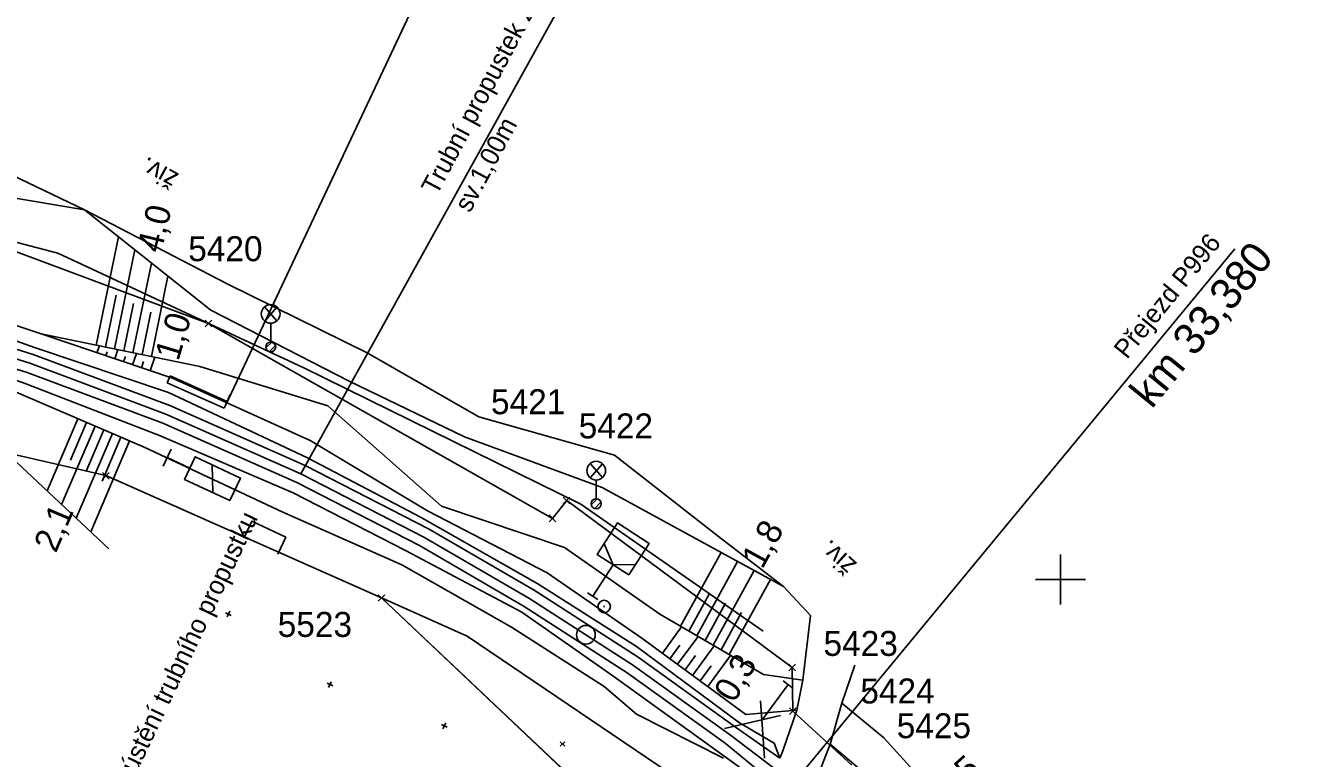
# Model space of a CAD drawing. Extents: x -805011 to -803920, y -1150790 to -1150234.
# Drawn here: x -804282.8 to -804179.8, y -1150514.3 to -1150455.7 of the extents above; entities that cross this region are included whole.
import ezdxf

# ---------------------------------------------------------------- set-up
doc = ezdxf.new("R2010")
doc.units = 0
for name, color, linetype in [('0381KM032-037P - Vrstva 1', 7, 'Continuous'), ('0381KM032-037P - Vrstva 17', 7, 'Continuous'), ('0381KM032-037P - Vrstva 19', 7, 'Continuous'), ('0381KM032-037P - Vrstva 25', 7, 'Continuous'), ('0381KM032-037P - Vrstva 4', 7, 'Continuous'), ('0381KM032-037P - Vrstva 43', 7, 'Continuous'), ('0381KM032-037P - Vrstva 48', 7, 'Continuous'), ('0381KM032-037P - Vrstva 49', 7, 'Continuous'), ('0381KM032-037P - Vrstva 51', 7, 'Continuous'), ('0381KM032-037P - Vrstva 55', 7, 'Continuous'), ('0381KM032-037P - Vrstva 7', 7, 'Continuous'), ('0381KM032-037P - Vrstva 9', 7, 'Continuous'), ('krizky_1000 - Vrstva 1', 7, 'Continuous'), ('szdc - hran DP', 7, 'Continuous'), ('szdc - szdc_cislo', 7, 'Continuous'), ('szdc - szdc_krizek', 7, 'Continuous')]:
    doc.layers.add(name, color=color, linetype=linetype)

msp = doc.modelspace()

# ---------------------------------------------------------------- linework, layer by layer
at = {"layer": '0381KM032-037P - Vrstva 1'}
msp.add_lwpolyline([(-804222.98, -1150515.09), (-804226.42, -1150512.48), (-804234.26, -1150506.83), (-804242.54, -1150501.49), (-804250.96, -1150496.61), (-804260.8, -1150491.55), (-804271.59, -1150486.76), (-804282.48, -1150482.69), (-804291.53, -1150479.85), (-804302.34, -1150477.08), (-804311.51, -1150475.27), (-804320.67, -1150473.88), (-804330.92, -1150472.81), (-804341.55, -1150472.27), (-804345.19, -1150472.22)], dxfattribs=at)
at = {"layer": '0381KM032-037P - Vrstva 17'}
msp.add_lwpolyline([(-804223.8, -1150504.14), (-804238.39, -1150493.96), (-804260.56, -1150483.05), (-804280.24, -1150473.89), (-804302.47, -1150468.07)], dxfattribs=at)
at = {"layer": '0381KM032-037P - Vrstva 19'}
msp.add_line((-804260.8, -1150491.55), (-804226.07, -1150428.82), dxfattribs=at)
at = {"layer": '0381KM032-037P - Vrstva 25'}
for p, q in [((-804263.7, -1150478.18), (-804262.71, -1150479.29)), ((-804263.69, -1150479.31), (-804262.71, -1150478.19)), ((-804263.21, -1150479.49), (-804263.21, -1150480.99)), ((-804263.6, -1150481.47), (-804263.13, -1150481)), ((-804263.33, -1150481.77), (-804262.83, -1150481.27)), ((-804237.65, -1150490.73), (-804236.66, -1150491.84)), ((-804237.64, -1150491.86), (-804236.66, -1150490.74)), ((-804237.16, -1150492.04), (-804237.16, -1150493.54)), ((-804237.55, -1150494.02), (-804237.08, -1150493.55)), ((-804237.28, -1150494.32), (-804236.78, -1150493.82))]:
    msp.add_line(p, q, dxfattribs=at)
for centre, radius in [((-804263.21, -1150478.74), 0.749), ((-804263.21, -1150481.39), 0.4), ((-804263.21, -1150481.39), 0.4), ((-804237.16, -1150491.29), 0.749), ((-804237.16, -1150493.94), 0.4), ((-804237.16, -1150493.94), 0.4)]:
    msp.add_circle(centre, radius, dxfattribs=at)
at = {"layer": '0381KM032-037P - Vrstva 4'}
for p, q in [((-804186.06, -1150473.54), (-804222.06, -1150517.12)), ((-804221.8, -1150508.42), (-804223.88, -1150511.23)), ((-804221.4, -1150508.72), (-804222.2, -1150508.12)), ((-804223.68, -1150514.31), (-804224, -1150509.71)), ((-804222.4, -1150510.9), (-804226.89, -1150511.93))]:
    msp.add_line(p, q, dxfattribs=at)
for points in [[(-804225.7, -1150511.47), (-804233.93, -1150505.38), (-804241.84, -1150500.35), (-804251.18, -1150495.03), (-804260.27, -1150490.25), (-804271.39, -1150485.02), (-804282.1, -1150481.42), (-804291.28, -1150478.15), (-804302, -1150475.62), (-804311.22, -1150473.82), (-804320.47, -1150472.35), (-804331.17, -1150471.28), (-804341.36, -1150470.84), (-804345.11, -1150470.79), (-804355.15, -1150471.09), (-804364.49, -1150471.64), (-804373.72, -1150472.46), (-804382.56, -1150473.46), (-804390.64, -1150474.3), (-804394.58, -1150474.82), (-804430.68, -1150479.4), (-804471.16, -1150484.87), (-804515.79, -1150490.21)], [(-804222.47, -1150514.31), (-804225.93, -1150511.88), (-804233.81, -1150506.22), (-804242.12, -1150500.85), (-804250.57, -1150495.96), (-804260.44, -1150490.89), (-804271.28, -1150486.07), (-804282.21, -1150481.99), (-804291.28, -1150479.14), (-804302.11, -1150476.36), (-804311.33, -1150474.54), (-804320.55, -1150473.14), (-804330.83, -1150472.06), (-804341.5, -1150471.52), (-804345.16, -1150471.47), (-804355.1, -1150471.64), (-804364.39, -1150472.17), (-804373.73, -1150473.02), (-804382.33, -1150473.97), (-804390.45, -1150474.97), (-804394.45, -1150475.48), (-804430.79, -1150480.07), (-804470.48, -1150485.06), (-804515.61, -1150490.8)], [(-804223.37, -1150515.97), (-804226.85, -1150513.1), (-804234.67, -1150507.48), (-804242.93, -1150502.16), (-804251.31, -1150497.29), (-804261.13, -1150492.25), (-804271.85, -1150487.49), (-804282.71, -1150483.42), (-804291.73, -1150480.59), (-804302.46, -1150477.85), (-804311.66, -1150476.01), (-804320.71, -1150474.65), (-804330.94, -1150473.58), (-804341.55, -1150473.05), (-804345.16, -1150472.99), (-804355.02, -1150473.16), (-804364.28, -1150473.69), (-804373.57, -1150474.51), (-804382.12, -1150475.46), (-804390.26, -1150476.46), (-804394.25, -1150476.96), (-804430.61, -1150481.56), (-804470.33, -1150486.56), (-804515.43, -1150492.3)], [(-804235.83, -1150507.71), (-804243.11, -1150502.63), (-804252.43, -1150497.68), (-804261.4, -1150493.06), (-804272.11, -1150488.47), (-804283.06, -1150484.22), (-804291.82, -1150481.32), (-804302.89, -1150478.85), (-804311.92, -1150476.81), (-804320.92, -1150475.47), (-804331.06, -1150474.34), (-804341.56, -1150473.81), (-804345.45, -1150473.75), (-804355.04, -1150473.96), (-804364.32, -1150474.45), (-804373.64, -1150475.34), (-804382.1, -1150476.35), (-804390.24, -1150477.29), (-804394.24, -1150477.85), (-804430.45, -1150482.3), (-804470.19, -1150487.36), (-804515.37, -1150493.06)], [(-804235.83, -1150507.71), (-804224.74, -1150515.72), (-804223.37, -1150515.97)], [(-804222.47, -1150514.31), (-804222.91, -1150513.11), (-804225.7, -1150511.47)]]:
    msp.add_lwpolyline(points, dxfattribs=at)
at = {"layer": '0381KM032-037P - Vrstva 43'}
msp.add_lwpolyline([(-804265.36, -1150496.69), (-804264.71, -1150495.33), (-804262, -1150496.62), (-804262.65, -1150497.98)], dxfattribs=at)
at = {"layer": '0381KM032-037P - Vrstva 48'}
for p, q in [((-804277.17, -1150481.25), (-804275.39, -1150472.58)), ((-804275.7, -1150481.55), (-804274.07, -1150473.62)), ((-804274.23, -1150481.85), (-804272.76, -1150474.67)), ((-804272.76, -1150482.15), (-804271.44, -1150475.71)), ((-804276.44, -1150481.4), (-804275.58, -1150477.25)), ((-804274.97, -1150481.7), (-804274.19, -1150477.92)), ((-804273.5, -1150482), (-804272.8, -1150478.59)), ((-804277.11, -1150481.85), (-804276.92, -1150481.3)), ((-804276.4, -1150482.09), (-804276.29, -1150481.77)), ((-804275.69, -1150482.33), (-804275.44, -1150481.6)), ((-804274.98, -1150482.57), (-804274.84, -1150482.16)), ((-804274.27, -1150482.81), (-804273.96, -1150481.91)), ((-804273.56, -1150483.05), (-804273.39, -1150482.55)), ((-804272.85, -1150483.29), (-804272.48, -1150482.21)), ((-804278.64, -1150487.13), (-804281.11, -1150492.91)), ((-804277.26, -1150487.72), (-804279.94, -1150494)), ((-804277.95, -1150487.43), (-804279.23, -1150490.44)), ((-804275.88, -1150488.31), (-804278.78, -1150495.09)), ((-804276.57, -1150488.02), (-804277.96, -1150491.28)), ((-804274.5, -1150488.9), (-804277.61, -1150496.19)), ((-804275.19, -1150488.6), (-804276.69, -1150492.12)), ((-804230.4, -1150503.75), (-804227.17, -1150497.84)), ((-804229.1, -1150504.51), (-804225.85, -1150498.56)), ((-804227.81, -1150505.26), (-804224.53, -1150499.28)), ((-804226.51, -1150506.02), (-804223.22, -1150500)), ((-804229.75, -1150504.13), (-804228.13, -1150501.17)), ((-804228.45, -1150504.88), (-804226.82, -1150501.9)), ((-804227.16, -1150505.64), (-804225.52, -1150502.64)), ((-804231.86, -1150505.91), (-804230.32, -1150503.8)), ((-804231.26, -1150506.35), (-804230.46, -1150505.26)), ((-804230.65, -1150506.79), (-804229.01, -1150504.56)), ((-804229.44, -1150507.68), (-804227.71, -1150505.32)), ((-804230.05, -1150507.24), (-804229.2, -1150506.09)), ((-804228.23, -1150508.57), (-804226.41, -1150506.08)), ((-804228.84, -1150508.12), (-804227.95, -1150506.91))]:
    msp.add_line(p, q, dxfattribs=at)
at = {"layer": '0381KM032-037P - Vrstva 49'}
for p, q in [((-804266.82, -1150502.66), (-804266.36, -1150502.88)), ((-804266.48, -1150502.54), (-804266.7, -1150503)), ((-804258.7, -1150508.31), (-804258.24, -1150508.53)), ((-804258.36, -1150508.19), (-804258.58, -1150508.65)), ((-804220.62, -1150508.07), (-804221.1, -1150510.47)), ((-804218.43, -1150513.19), (-804217.51, -1150509.9)), ((-804214.14, -1150512.69), (-804217.51, -1150509.9)), ((-804249.54, -1150511.61), (-804249.08, -1150511.83)), ((-804249.2, -1150511.49), (-804249.42, -1150511.95)), ((-804239.68, -1150513.36), (-804240.04, -1150513)), ((-804239.68, -1150513), (-804240.04, -1150513.36)), ((-804218.43, -1150513.19), (-804219.46, -1150515.79)), ((-804216.26, -1150515.03), (-804218.43, -1150513.19))]:
    msp.add_line(p, q, dxfattribs=at)
for points in [[(-804320.34, -1150463.27), (-804278.12, -1150470.41)], [(-804221.1, -1150510.47), (-804225.19, -1150510.8), (-804233.52, -1150504.69), (-804241.09, -1150499.46), (-804250.66, -1150494.51), (-804260.04, -1150488.87), (-804271.07, -1150483.89), (-804281.58, -1150480.34), (-804290.68, -1150477.29), (-804301.47, -1150474.53), (-804310.76, -1150472.67), (-804320.3, -1150471.51), (-804330.99, -1150470.46), (-804340.83, -1150469.83), (-804345.1, -1150470.19), (-804354.95, -1150469.89)], [(-804222.18, -1150500.57), (-804236.67, -1150492.64), (-804247.69, -1150488.59), (-804256.93, -1150484.13), (-804267.99, -1150478.45), (-804278.12, -1150470.41)], [(-804226.97, -1150514.32), (-804233.94, -1150510.78), (-804236.52, -1150508.57), (-804243.93, -1150503.82), (-804252.72, -1150498.82), (-804262.25, -1150494.6), (-804273.33, -1150489.4), (-804283.59, -1150485.01), (-804292.89, -1150482.47), (-804303.02, -1150479.68), (-804312.2, -1150478.16), (-804321.12, -1150476.62), (-804331.14, -1150475.24), (-804341.8, -1150475.06), (-804345.41, -1150474.87), (-804355.14, -1150475.34), (-804364.22, -1150475.73), (-804373.58, -1150476.33), (-804382.14, -1150477.38), (-804390.01, -1150478.23), (-804394.36, -1150478.78), (-804430.35, -1150482.91), (-804470.16, -1150488.05), (-804515.21, -1150493.93)], [(-804276.15, -1150497.56), (-804284.03, -1150490.16), (-804299.15, -1150485.83), (-804306.89, -1150483.98), (-804317.28, -1150482.7), (-804327.05, -1150481.84), (-804338.6, -1150481.41), (-804350.55, -1150480.59), (-804360.54, -1150481.11), (-804374.96, -1150483.29), (-804385.39, -1150485.41), (-804391.71, -1150485.5), (-804430.73, -1150489.32), (-804470.3, -1150492.85), (-804514.17, -1150497.56)], [(-804220.62, -1150508.07), (-804223.76, -1150507.62), (-804232.08, -1150502.77), (-804239.7, -1150497.43), (-804249.53, -1150494.12), (-804258.64, -1150486.1), (-804268.88, -1150482.95), (-804281.58, -1150480.34)], [(-804222.18, -1150500.57), (-804220.01, -1150502.88), (-804220.62, -1150508.07)], [(-804179.78, -1150547.3), (-804187.89, -1150541.65), (-804195.9, -1150532.8), (-804214.14, -1150512.69)]]:
    msp.add_lwpolyline(points, dxfattribs=at)
at = {"layer": '0381KM032-037P - Vrstva 51'}
for points in [[(-804222.47, -1150514.31), (-804222.23, -1150513.73), (-804221.1, -1150510.47), (-804220.62, -1150508.07), (-804220.01, -1150502.88), (-804222.18, -1150500.57), (-804227.38, -1150496.55), (-804235.69, -1150490.06), (-804246.55, -1150486.97), (-804255.48, -1150481.87), (-804266.7, -1150476.32), (-804278.12, -1150470.41), (-804293.62, -1150463)], [(-804219.78, -1150516.58), (-804219.46, -1150515.79), (-804218.43, -1150513.19), (-804217.51, -1150509.9), (-804216.47, -1150506.86)]]:
    msp.add_lwpolyline(points, dxfattribs=at)
at = {"layer": '0381KM032-037P - Vrstva 55'}
msp.add_lwpolyline([(-804254.35, -1150501.48), (-804247.48, -1150504.53), (-804225.97, -1150519.11), (-804228.6, -1150522.11), (-804232.32, -1150522.3)], close=True, dxfattribs=at)
at = {"layer": '0381KM032-037P - Vrstva 7'}
for p, q in [((-804271.17, -1150489.56), (-804271.81, -1150490.92)), ((-804267.9, -1150490.82), (-804267.84, -1150493.06)), ((-804235.81, -1150498.82), (-804237.44, -1150501.34)), ((-804237.86, -1150501.07), (-804237.02, -1150501.61)), ((-804236.57, -1150502.17), (-804236.47, -1150502.17))]:
    msp.add_line(p, q, dxfattribs=at)
for points in [[(-804271.49, -1150490.24), (-804269.68, -1150491.09), (-804270.1, -1150491.99), (-804266.48, -1150493.69), (-804265.63, -1150491.88), (-804269.25, -1150490.18), (-804269.68, -1150491.09)], [(-804235.81, -1150498.82), (-804234.55, -1150499.63), (-804232.93, -1150497.11), (-804235.45, -1150495.48), (-804237.07, -1150498.01), (-804235.81, -1150498.82)], [(-804236.53, -1150497.16), (-804235.81, -1150498.82), (-804234.01, -1150498.79)]]:
    msp.add_lwpolyline(points, dxfattribs=at)
for centre, radius in [((-804236.52, -1150502.17), 0.5), ((-804237.98, -1150504.43), 0.75)]:
    msp.add_circle(centre, radius, dxfattribs=at)
at = {"layer": '0381KM032-037P - Vrstva 9'}
for p, q in [((-804237.76, -1150424.25), (-804266.81, -1150486.01)), ((-804271.26, -1150483.71), (-804271.5, -1150484.26)), ((-804266.69, -1150485.74), (-804271.26, -1150483.71)), ((-804271.5, -1150484.26), (-804266.93, -1150486.28)), ((-804266.93, -1150486.28), (-804266.69, -1150485.74)), ((-804266.69, -1150485.74), (-804266.45, -1150485.19))]:
    msp.add_line(p, q, dxfattribs=at)
at = {"layer": 'krizky_1000 - Vrstva 1'}
for points in [[(-804200, -1150498), (-804200, -1150502)], [(-804202, -1150500), (-804198, -1150500)]]:
    msp.add_lwpolyline(points, dxfattribs=at)
at = {"layer": 'szdc - hran DP'}
for p, q in [((-804301.77, -1150466.98), (-804268.19, -1150479.5)), ((-804268.19, -1150479.5), (-804240.65, -1150495.11)), ((-804276.4, -1150491.69), (-804317.89, -1150482.17)), ((-804254.35, -1150501.48), (-804276.4, -1150491.69)), ((-804240.65, -1150495.11), (-804239.52, -1150493.68)), ((-804239.52, -1150493.68), (-804221.47, -1150507.06)), ((-804232.32, -1150522.3), (-804254.35, -1150501.48)), ((-804221.47, -1150507.06), (-804221.41, -1150510.55)), ((-804221.41, -1150510.55), (-804216.71, -1150514.88))]:
    msp.add_line(p, q, dxfattribs=at)
at = {"layer": 'szdc - szdc_krizek'}
for p, q in [((-804267.93, -1150479.77), (-804268.46, -1150479.24)), ((-804268.46, -1150479.77), (-804267.93, -1150479.24)), ((-804276.14, -1150491.96), (-804276.67, -1150491.43)), ((-804276.67, -1150491.96), (-804276.14, -1150491.43)), ((-804239.26, -1150493.95), (-804239.79, -1150493.42)), ((-804239.79, -1150493.95), (-804239.26, -1150493.42)), ((-804240.39, -1150495.38), (-804240.92, -1150494.84)), ((-804240.92, -1150495.38), (-804240.39, -1150494.84)), ((-804254.08, -1150501.75), (-804254.62, -1150501.22)), ((-804254.62, -1150501.75), (-804254.08, -1150501.22)), ((-804221.21, -1150507.32), (-804221.74, -1150506.79)), ((-804221.74, -1150507.32), (-804221.21, -1150506.79)), ((-804221.15, -1150510.81), (-804221.68, -1150510.28)), ((-804221.68, -1150510.81), (-804221.15, -1150510.28))]:
    msp.add_line(p, q, dxfattribs=at)

# ---------------------------------------------------------------- texts
at = {"layer": '0381KM032-037P - Vrstva 19'}
for s, p in [('Trubní propustek zasypán', (-804249.91, -1150469.3)), ('sv.1,00m', (-804247.26, -1150470.71))]:
    msp.add_text(s, height=1.5, rotation=61.9777, dxfattribs=at).set_placement(p)
at = {"layer": '0381KM032-037P - Vrstva 4'}
for s, height, p in [('Přejezd P996', 1.5, (-804194.69, -1150482.43)), ('km 33,380', 2.5, (-804192.7, -1150486.41))]:
    msp.add_text(s, height=height, rotation=50.856, dxfattribs=at).set_placement(p)
at = {"layer": '0381KM032-037P - Vrstva 43'}
msp.add_text('vyústění trubního propustku', height=1.5, rotation=64.5558, dxfattribs=at).set_placement((-804274.83, -1150517.39))
at = {"layer": '0381KM032-037P - Vrstva 48'}
for s, rotation, p in [('4,0', 76.5616, (-804271.98, -1150473.92)), ('1,0', 73.3867, (-804270.6, -1150482.58)), ('2,1', 66.8351, (-804280.4, -1150497.95)), ('1,8', 61.3093, (-804223.87, -1150499.25)), ('0,3', 59.7607, (-804226.12, -1150509.96)), ('0,5', 42.198, (-804209.02, -1150517.88))]:
    msp.add_text(s, height=2, rotation=rotation, dxfattribs=at).set_placement(p)
at = {"layer": '0381KM032-037P - Vrstva 51'}
for rotation, p in [(151.1139, (-804270.48, -1150467.55)), (138.2966, (-804216.22, -1150498.71))]:
    msp.add_text('živ.', height=1.5, rotation=rotation, dxfattribs=at).set_placement(p)
at = {"layer": 'szdc - szdc_cislo'}
for s, p in [('5420', (-804269.81, -1150474.52)), ('5421', (-804245.58, -1150486.77)), ('5422', (-804238.56, -1150488.71)), ('5523', (-804262.65, -1150504.6)), ('5423', (-804218.97, -1150506.12)), ('5424', (-804216.02, -1150509.93)), ('5425', (-804213.11, -1150512.71))]:
    msp.add_text(s, height=2, dxfattribs=at).set_placement(p)

doc.saveas('drawing.dxf')
